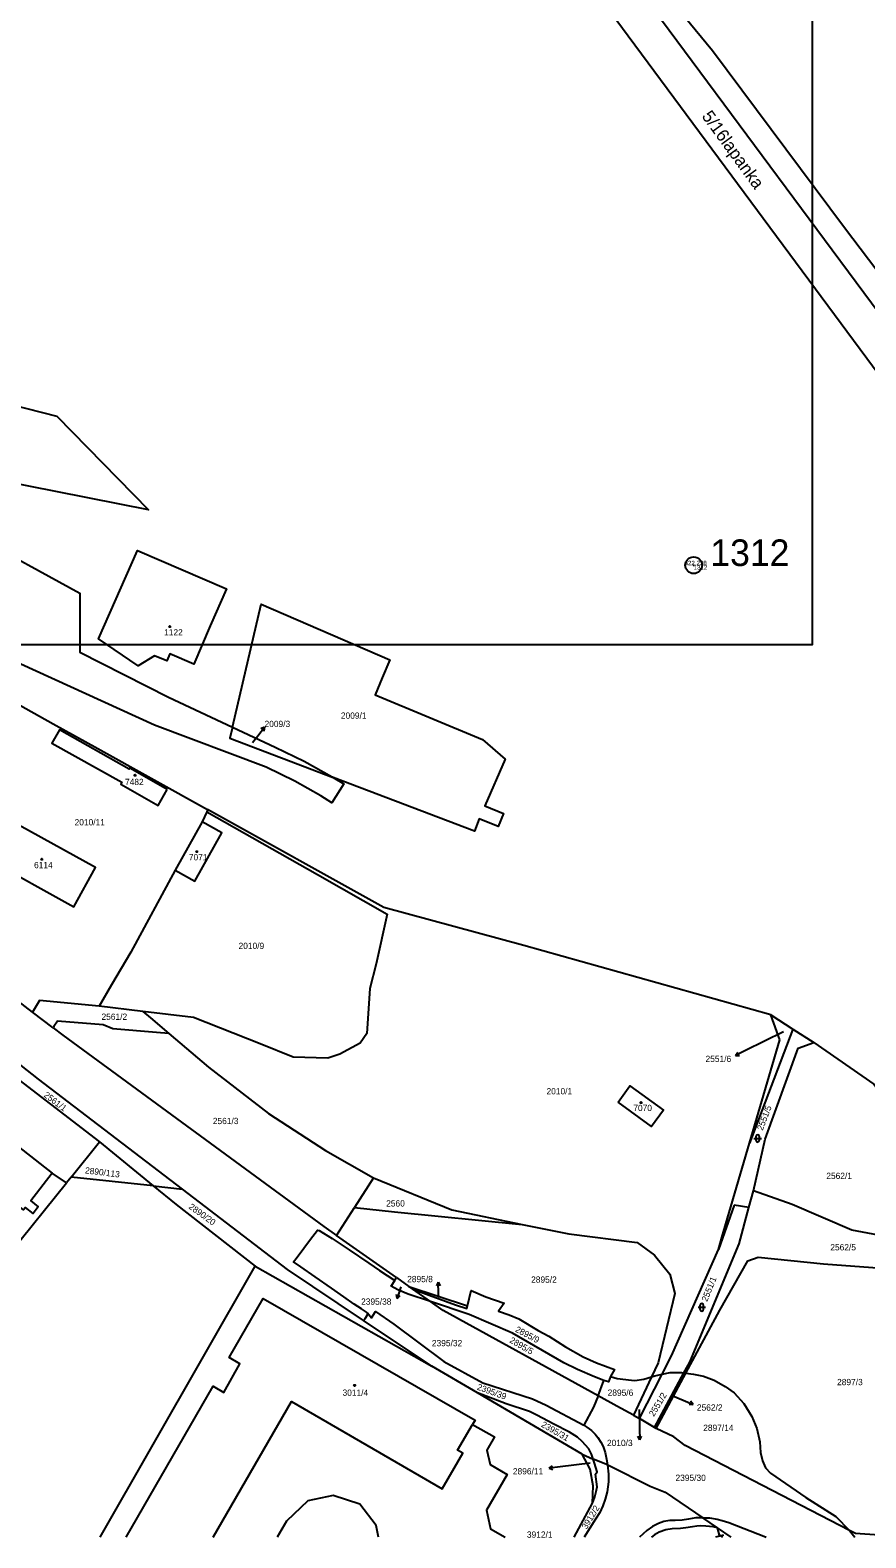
# Model space of a CAD drawing. Extents: x -667048 to -665920, y -1108425 to -1107247.
# Drawn here: x -666456.4 to -666229.9, y -1108425.3 to -1108016.8 of the extents above; entities that cross this region are included whole.
import ezdxf

# ---------------------------------------------------------------- set-up
doc = ezdxf.new("R2010")
doc.units = 0
for name, color, linetype in [('Default', 7, 'Continuous'), ('Hranice parcel', 7, 'Continuous'), ('Parcelní čísla', 7, 'Continuous'), ('Pop_ PČ_ popisy', 7, 'Continuous'), ('Vrstva 1', 7, 'Continuous'), ('Vrstva 2', 7, 'Continuous'), ('Vrstva 60', 7, 'Continuous'), ('Vrstva 61', 7, 'Continuous'), ('Značky budov', 7, 'Continuous'), ('Značky kultur', 7, 'Continuous')]:
    doc.layers.add(name, color=color, linetype=linetype)

# ---------------------------------------------------------------- blocks, each defined once
blk = doc.blocks.new('4.021')
at = {"layer": 'Default'}
blk.add_circle((-7, 1), 175, dxfattribs=at)
blk = doc.blocks.new('3.161')
at = {"layer": 'Default'}
for p, q in [((-1000, 1000), (1000, 1000)), ((-500, 1500), (-500, 500)), ((500, 500), (500, 1500))]:
    blk.add_line(p, q, dxfattribs=at)
for centre, start, end in [((0, 1500), 0, 180), ((0, 500), 180, 359.98789)]:
    blk.add_arc(centre, 500, start, end, dxfattribs=at)
blk = doc.blocks.new('10291')
at = {"layer": 'Default'}
for p, q in [((0, 3001), (-500, 2001)), ((0, 1), (0, 3001)), ((0, 3001), (500, 2001))]:
    blk.add_line(p, q, dxfattribs=at)

msp = doc.modelspace()

# ---------------------------------------------------------------- linework, layer by layer
at = {"layer": 'Hranice parcel'}
for points in [[(-666367.6, -1107733.37), (-666382.25, -1107746.6), (-666386.05, -1107757.21), (-666386.95, -1107822.21), (-666377, -1107854.78), (-666312.82, -1107976.82), (-666211.46, -1108113.47), (-666205.22, -1108120.66), (-666194.69, -1108126.35), (-666183.7, -1108127.05), (-666164.66, -1108121.36)], [(-666308.12, -1107969.91), (-666292.75, -1107996.41), (-666271.46, -1108022.33), (-666235.68, -1108070.26), (-666212.14, -1108101.26), (-666198.27, -1108121.92), (-666187.57, -1108125.3), (-666164.66, -1108121.36)], [(-666320.26, -1107983.17), (-666217.49, -1108122.07), (-666204.14, -1108132.75)], [(-666473.73, -1108137.06), (-666465.43, -1108117.23), (-666449.11, -1108121.4), (-666424.27, -1108146.74), (-666473.73, -1108137.06)], [(-666374.21, -1108219.28), (-666371.36, -1108220.98), (-666374.62, -1108226.13), (-666377.53, -1108224.23), (-666384.61, -1108220.26), (-666392.36, -1108216.54), (-666422.61, -1108205.11), (-666463.99, -1108186.24), (-666475.13, -1108181.04), (-666489.53, -1108173.36), (-666546.91, -1108141.77), (-666554.72, -1108137.47)], [(-666471.97, -1108153.48), (-666442.88, -1108169.37), (-666442.9, -1108185.32), (-666418.86, -1108197.5), (-666401.5, -1108205.65)], [(-666407.58, -1108178.17), (-666412.03, -1108188.62), (-666418.53, -1108185.84), (-666419.34, -1108187.72), (-666422.62, -1108186.32), (-666427.12, -1108189.02), (-666437.79, -1108181.77), (-666427.3, -1108157.82), (-666403.13, -1108168.19), (-666407.58, -1108178.17)], [(-666401.5, -1108205.65), (-666393.74, -1108172.32), (-666358.86, -1108187.38), (-666360.92, -1108192.34), (-666362.84, -1108196.95), (-666333.78, -1108209.04), (-666327.62, -1108214.37), (-666333.14, -1108226.96), (-666328.04, -1108229.05), (-666329.5, -1108232.56), (-666334.63, -1108230.51), (-666335.97, -1108233.85), (-666374.21, -1108219.28)], [(-666466.46, -1108195.64), (-666450.09, -1108204.73), (-666437.99, -1108211.45)], [(-666419.21, -1108222.58), (-666429.35, -1108216.78), (-666429.5, -1108217), (-666448.42, -1108206.41), (-666450.49, -1108209.99), (-666431.49, -1108220.59), (-666431.79, -1108221.09), (-666421.66, -1108226.87), (-666419.21, -1108222.58)], [(-666401.5, -1108205.65), (-666402.19, -1108208.62), (-666374.21, -1108219.28)], [(-666401.5, -1108205.65), (-666389.91, -1108211.08), (-666382.07, -1108214.87), (-666374.46, -1108219.13), (-666374.21, -1108219.28)], [(-666437.99, -1108211.45), (-666408.25, -1108227.98)], [(-666408.25, -1108227.98), (-666408.51, -1108228.56)], [(-666255.62, -1108283.59), (-666322.55, -1108264.86), (-666360.48, -1108254.53), (-666408.25, -1108227.98)], [(-666455.68, -1108282.86), (-666482, -1108262.62), (-666523.39, -1108230.78)], [(-666467.96, -1108241.34), (-666444.49, -1108254.32), (-666438.63, -1108243.72), (-666462, -1108230.81), (-666467.96, -1108241.34)], [(-666408.51, -1108228.56), (-666378.44, -1108245.6), (-666359.63, -1108256.35), (-666362.62, -1108269.83), (-666364.28, -1108276.45), (-666365.14, -1108288.63), (-666366.89, -1108291.25), (-666372.41, -1108294.29), (-666375.66, -1108295.31), (-666385.09, -1108295.09), (-666394.04, -1108291.44), (-666412.1, -1108284.35), (-666425.85, -1108282.67)], [(-666417.09, -1108244.44), (-666411.76, -1108247.42), (-666404.44, -1108234.31), (-666409.74, -1108231.28)], [(-666409.74, -1108231.28), (-666417.09, -1108244.44)], [(-666408.51, -1108228.56), (-666409.74, -1108231.28)], [(-666417.09, -1108244.44), (-666429.08, -1108266.61), (-666434.28, -1108275.51), (-666437.63, -1108281.23)], [(-666415.08, -1108330.81), (-666454.07, -1108301), (-666489.57, -1108273.1)], [(-666491.9, -1108276.3), (-666437.54, -1108318.05)], [(-666437.63, -1108281.23), (-666453.83, -1108279.75), (-666455.68, -1108282.86)], [(-666425.85, -1108282.67), (-666437.63, -1108281.23)], [(-666450.14, -1108287.12), (-666455.68, -1108282.86)], [(-666418.73, -1108288.7), (-666422.12, -1108288.41), (-666433.93, -1108287.4), (-666436.57, -1108286.29), (-666448.94, -1108285.28), (-666449.93, -1108286.8), (-666450.14, -1108287.12)], [(-666425.85, -1108282.67), (-666423.75, -1108284.46), (-666418.73, -1108288.7)], [(-666255.62, -1108283.59), (-666249.63, -1108287.46)], [(-666253.19, -1108290.38), (-666255.62, -1108283.59)], [(-666450.14, -1108287.12), (-666447.53, -1108289.14), (-666376.75, -1108340.94), (-666373.31, -1108343.36)], [(-666418.73, -1108288.7), (-666408.04, -1108297.75), (-666391.74, -1108310.31)], [(-666249.63, -1108287.46), (-666261.4, -1108318.34)], [(-666249.63, -1108287.46), (-666243.99, -1108291.1)], [(-666261.4, -1108318.34), (-666253.19, -1108290.38)], [(-666260.35, -1108331.3), (-666257.12, -1108317.27), (-666248.18, -1108292.62), (-666243.99, -1108291.1)], [(-666243.99, -1108291.1), (-666227.7, -1108302.43), (-666213.72, -1108320.63), (-666200.9, -1108335.77)], [(-666482.29, -1108301.57), (-666450.39, -1108326.54)], [(-666296.97, -1108307.26), (-666293.81, -1108302.8), (-666284.72, -1108309.42), (-666287.91, -1108313.84), (-666296.97, -1108307.26)], [(-666450.39, -1108326.54), (-666456.2, -1108333.99), (-666454.16, -1108335.65), (-666455.55, -1108337.43), (-666457.59, -1108335.76), (-666458.13, -1108336.46), (-666493.26, -1108308.83)], [(-666391.74, -1108310.31), (-666376.27, -1108320.34), (-666363.26, -1108327.81)], [(-666445.24, -1108327.58), (-666437.54, -1108318.05)], [(-666437.54, -1108318.05), (-666422.97, -1108329.91)], [(-666268.91, -1108343.91), (-666261.4, -1108318.34)], [(-666477.13, -1108367.05), (-666446.5, -1108329.13)], [(-666446.5, -1108329.13), (-666450.39, -1108326.54)], [(-666445.24, -1108327.58), (-666446.5, -1108329.13)], [(-666422.97, -1108329.91), (-666445.24, -1108327.58)], [(-666422.97, -1108329.91), (-666416.75, -1108334.97), (-666395.38, -1108351.66)], [(-666422.97, -1108329.91), (-666415.08, -1108330.81)], [(-666363.26, -1108327.81), (-666368.45, -1108335.83)], [(-666363.26, -1108327.81), (-666342.05, -1108336.4), (-666322.97, -1108340.44)], [(-666386.59, -1108352.59), (-666415.08, -1108330.81)], [(-666261.55, -1108335.79), (-666260.35, -1108331.3)], [(-666205.05, -1108348.04), (-666220.61, -1108344.36), (-666233.7, -1108341.93), (-666249.84, -1108334.97), (-666260.35, -1108331.3)], [(-666373.31, -1108343.36), (-666368.45, -1108335.83)], [(-666368.45, -1108335.83), (-666357.58, -1108336.96), (-666322.97, -1108340.44)], [(-666279.15, -1108380.61), (-666277.57, -1108377.67), (-666264.17, -1108345.61), (-666261.55, -1108335.79)], [(-666265.59, -1108335.2), (-666269.83, -1108347.17)], [(-666261.55, -1108335.79), (-666265.59, -1108335.2)], [(-666364.9, -1108364.38), (-666366.57, -1108363.3), (-666368.57, -1108362.01), (-666371.33, -1108359.99), (-666374.7, -1108357.64), (-666379.11, -1108354.57), (-666383, -1108351.88), (-666384.97, -1108350.52), (-666384.03, -1108349.28), (-666380.36, -1108344.41), (-666378.47, -1108341.91), (-666378, -1108342.01), (-666374.5, -1108344.22), (-666369.85, -1108347.27), (-666364.53, -1108350.86), (-666361.71, -1108352.83), (-666357.56, -1108355.54)], [(-666322.97, -1108340.44), (-666310.32, -1108342.9), (-666291.83, -1108345.28), (-666287.13, -1108348.72), (-666283.03, -1108353.89), (-666281.62, -1108359.1), (-666286.15, -1108377.89), (-666287.92, -1108381.66)], [(-666357.1, -1108354.78), (-666373.31, -1108343.36)], [(-666269.83, -1108347.17), (-666268.91, -1108343.91)], [(-666285.07, -1108380.95), (-666282.51, -1108375.95), (-666269.83, -1108347.17)], [(-666278.65, -1108380.68), (-666269.46, -1108363.62), (-666261.84, -1108350.27), (-666259.02, -1108349.27), (-666241.32, -1108351.03), (-666206.04, -1108353.64)], [(-666437.4, -1108425.13), (-666395.38, -1108351.66)], [(-666395.38, -1108351.66), (-666347.5, -1108378.83)], [(-666366, -1108366.41), (-666386.59, -1108352.59)], [(-666357.56, -1108355.54), (-666357.1, -1108354.78)], [(-666357.1, -1108354.78), (-666353.7, -1108357.17)], [(-666347.85, -1108361.27), (-666353.88, -1108359.26), (-666356.74, -1108358.14), (-666358.52, -1108357.13), (-666357.56, -1108355.54)], [(-666353.7, -1108357.17), (-666337.81, -1108362.46)], [(-666352.64, -1108357.91), (-666353.7, -1108357.17)], [(-666352.64, -1108357.91), (-666341.1, -1108362.21), (-666337.98, -1108363.21), (-666337.81, -1108362.46)], [(-666347.85, -1108361.27), (-666352.64, -1108357.91)], [(-666337.81, -1108362.46), (-666336.87, -1108358.32), (-666332.81, -1108360.01), (-666327.86, -1108361.7), (-666329.44, -1108363.85), (-666326.55, -1108364.92), (-666323.95, -1108365.97), (-666318.63, -1108369.09), (-666315.78, -1108370.67), (-666311.26, -1108373.59), (-666306.46, -1108376.27), (-666302.83, -1108377.87), (-666297.96, -1108379.71), (-666299.11, -1108381.58)], [(-666430.36, -1108425.13), (-666406.75, -1108384.24), (-666403.85, -1108385.91), (-666399.54, -1108378.12), (-666402.4, -1108376.48), (-666393.2, -1108360.44), (-666335.78, -1108393.39), (-666336.48, -1108394.61)], [(-666302.44, -1108386.81), (-666344.42, -1108363.68), (-666347.85, -1108361.27)], [(-666300.83, -1108382.64), (-666303.4, -1108381.69), (-666308.04, -1108379.73), (-666311.68, -1108377.92), (-666325.67, -1108369.89), (-666337.35, -1108364.78), (-666347.85, -1108361.27)], [(-666366, -1108366.41), (-666365.6, -1108365.88), (-666364.88, -1108364.87), (-666364.9, -1108364.38)], [(-666347.5, -1108378.83), (-666366, -1108366.41)], [(-666364.9, -1108364.38), (-666363.86, -1108365.68), (-666362.8, -1108363.95), (-666357.8, -1108367.37), (-666344.24, -1108377.57), (-666333.66, -1108383.3), (-666320.2, -1108387.65), (-666316.52, -1108389.38), (-666306.33, -1108394.82)], [(-666335.15, -1108386.04), (-666347.5, -1108378.83)], [(-666302.44, -1108386.81), (-666300.83, -1108382.64)], [(-666299.11, -1108381.58), (-666299.57, -1108383.03), (-666300.83, -1108382.64)], [(-666299.11, -1108381.58), (-666297.29, -1108382.14), (-666293.34, -1108382.55), (-666292.5, -1108382.65), (-666290.01, -1108382.34), (-666287.92, -1108381.66)], [(-666287.92, -1108381.66), (-666292.79, -1108392.06)], [(-666291.22, -1108392.99), (-666285.07, -1108380.95)], [(-666287.92, -1108381.66), (-666287.06, -1108381.38), (-666285.07, -1108380.95)], [(-666287.11, -1108395.41), (-666279.15, -1108380.61)], [(-666286.71, -1108395.64), (-666278.65, -1108380.68)], [(-666285.07, -1108380.95), (-666282.87, -1108380.48), (-666279.71, -1108380.54), (-666279.15, -1108380.61)], [(-666279.15, -1108380.61), (-666278.65, -1108380.68)], [(-666278.65, -1108380.68), (-666276.59, -1108380.95), (-666273.9, -1108381.53), (-666270.98, -1108382.57), (-666267.98, -1108384.28), (-666265.59, -1108386), (-666262.9, -1108388.91), (-666260.76, -1108392.4), (-666259.4, -1108395.64), (-666258.58, -1108399.31), (-666258.44, -1108402.2), (-666257.89, -1108404.42), (-666257.05, -1108406.31), (-666255.7, -1108407.75), (-666246.1, -1108414.35), (-666238.04, -1108419.48), (-666234.25, -1108423.31)], [(-666303.74, -1108403.96), (-666304.19, -1108402.61), (-666304.9, -1108401.22), (-666306.72, -1108399.17), (-666308.02, -1108398.06), (-666310.21, -1108396.65), (-666314.41, -1108394.48), (-666319.01, -1108392.11), (-666321.04, -1108391.06), (-666327.38, -1108388.99), (-666335.15, -1108386.04)], [(-666306.78, -1108402.61), (-666335.15, -1108386.04)], [(-666302.44, -1108386.81), (-666303.64, -1108389.92), (-666306.33, -1108394.82)], [(-666292.79, -1108392.06), (-666297.33, -1108389.63), (-666302.44, -1108386.81)], [(-666406.78, -1108425.13), (-666385.55, -1108388.35), (-666344.66, -1108411.98), (-666341.45, -1108406.44), (-666339.09, -1108402.36), (-666340.5, -1108401.55), (-666336.48, -1108394.61)], [(-666336.48, -1108394.61), (-666330.52, -1108397.91), (-666332.57, -1108401.53), (-666331.7, -1108405.44), (-666327.05, -1108408.18), (-666332.64, -1108417.78), (-666331.62, -1108422.9), (-666327.57, -1108425.13)], [(-666306.33, -1108394.82), (-666305.51, -1108395.28), (-666304.25, -1108396.24), (-666303.25, -1108397.23), (-666302.51, -1108398.11), (-666301.7, -1108399.37), (-666301.09, -1108400.54), (-666300.51, -1108402.17), (-666300.16, -1108403.95), (-666299.9, -1108405.54)], [(-666292.79, -1108392.06), (-666291.22, -1108392.99)], [(-666287.11, -1108395.41), (-666291.22, -1108392.99)], [(-666286.71, -1108395.64), (-666287.11, -1108395.41)], [(-666234.25, -1108423.31), (-666278.79, -1108400.31), (-666281.92, -1108397.97), (-666286.71, -1108395.64)], [(-666303.92, -1108415.9), (-666303.73, -1108411.23), (-666304.56, -1108406.7), (-666306.78, -1108402.61)], [(-666306.78, -1108402.61), (-666303.74, -1108403.96)], [(-666299.9, -1108405.54), (-666299.59, -1108408.06), (-666299.62, -1108410.12), (-666299.76, -1108411.51), (-666299.97, -1108412.84), (-666300.49, -1108414.85), (-666301.1, -1108416.66), (-666301.93, -1108418.4), (-666303.11, -1108420.24), (-666306.16, -1108425.13)], [(-666303.92, -1108415.9), (-666303.34, -1108414.22), (-666302.92, -1108412.73), (-666302.68, -1108411.47), (-666303.12, -1108408.08), (-666302.66, -1108407.46), (-666303.39, -1108405.04), (-666303.74, -1108403.96)], [(-666299.9, -1108405.54), (-666303.74, -1108403.96)], [(-666299.9, -1108405.54), (-666299.4, -1108405.74), (-666288.36, -1108411.3), (-666284.24, -1108412.95), (-666274.07, -1108419.88)], [(-666361.9, -1108425.13), (-666362.54, -1108421.93), (-666367.04, -1108416.19), (-666374.25, -1108413.84), (-666381.11, -1108415.25), (-666386.9, -1108420.76), (-666389.42, -1108425.13)], [(-666308.94, -1108425.13), (-666303.92, -1108415.9)], [(-666274.07, -1108419.88), (-666275.9, -1108419.91), (-666277.94, -1108420.2), (-666279.68, -1108420.47), (-666281.52, -1108420.56), (-666282.99, -1108420.62), (-666284.62, -1108420.91), (-666286.08, -1108421.41), (-666287.68, -1108422.2), (-666289.26, -1108423.32), (-666291.17, -1108425.13)], [(-666274.07, -1108419.88), (-666272.27, -1108419.9), (-666270.12, -1108420.23), (-666268.76, -1108420.57), (-666267.02, -1108421.16), (-666262.8, -1108422.81), (-666257.54, -1108424.88), (-666256.92, -1108425.13)], [(-666270.11, -1108422.58), (-666274.07, -1108419.88)], [(-666270.11, -1108422.58), (-666271.23, -1108422.32), (-666273.22, -1108422.1), (-666274.61, -1108422.09), (-666275.67, -1108422.17), (-666276.81, -1108422.33), (-666278.65, -1108422.62), (-666280.06, -1108422.75), (-666282.31, -1108422.84), (-666284.08, -1108423.09), (-666285.84, -1108423.73), (-666287.14, -1108424.53), (-666287.94, -1108425.11), (-666287.96, -1108425.13)], [(-666266.36, -1108425.13), (-666270.11, -1108422.58)], [(-666268.61, -1108425.13), (-666269.55, -1108424.58), (-666270.11, -1108422.58)], [(-666226.29, -1108424.56), (-666232.68, -1108424.12), (-666234.25, -1108423.31)], [(-666234.25, -1108423.31), (-666232.82, -1108425.13)], [(-666308.94, -1108425.13), (-666308.94, -1108425.13)], [(-666308.94, -1108425.13), (-666308.94, -1108425.13)]]:
    msp.add_lwpolyline(points, dxfattribs=at)
at = {"layer": 'Pop_ PČ_ popisy'}
for points in [[(-666396.06, -1108209.81), (-666394.67, -1108208.01)], [(-666252.14, -1108288.25), (-666262.5, -1108293.3)], [(-666355.87, -1108357.29), (-666355.97, -1108357.6)], [(-666345.6, -1108360.16), (-666345.66, -1108359.04)], [(-666282.14, -1108386.79), (-666279.41, -1108387.96)], [(-666291.27, -1108390.49), (-666291.21, -1108395.74)], [(-666304.61, -1108405.06), (-666312.75, -1108406.06)], [(-666268.46, -1108424.55), (-666270.6, -1108425.13)]]:
    msp.add_lwpolyline(points, dxfattribs=at)
at = {"layer": 'Vrstva 1'}
msp.add_line((-666276.68, -1108161.79), (-666276.38, -1108161.79), dxfattribs=at)
msp.add_circle((-666276.53, -1108161.79), 2.27, dxfattribs=at)
at = {"layer": 'Vrstva 2'}
msp.add_lwpolyline([(-666838.39, -1107343.37), (-666244.39, -1107343.37), (-666244.39, -1108183.37), (-666838.39, -1108183.37)], close=True, dxfattribs=at)
at = {"layer": 'Vrstva 60'}
for p, q in [((-666276.53, -1108161.79), (-666276.53, -1108161.79)), ((-666276.51, -1108161.79), (-666276.51, -1108161.79))]:
    msp.add_line(p, q, dxfattribs=at)

# ---------------------------------------------------------------- block references
at = {"layer": 'Pop_ PČ_ popisy'}
for p, xscale, yscale, rotation in [((-666394.67, -1108208.01), 0.0010000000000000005, 0.0010000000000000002, -38.00000002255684), ((-666262.5, -1108293.3), 0.001, 0.0010000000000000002, 116.0000000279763), ((-666355.97, -1108357.6), 0.0010000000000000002, 0.0010000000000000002, 162.00000007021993), ((-666345.66, -1108359.04), 0.001, 0.0010000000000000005, 2.9999999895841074), ((-666279.41, -1108387.96), 0.0010000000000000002, 0.001, -113.0000000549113), ((-666291.21, -1108395.74), 0.0010000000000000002, 0.0010000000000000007, -179.00000011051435), ((-666312.75, -1108406.06), 0.0010000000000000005, 0.0010000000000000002, 97.00000001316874)]:
    msp.add_blockref('10291', p, dxfattribs=dict(at, xscale=xscale, yscale=yscale, rotation=rotation))
at = {"layer": 'Značky budov', "xscale": 0.0010000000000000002, "yscale": 0.0010000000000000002}
for p in [(-666418.48, -1108178.41), (-666427.9, -1108218.69), (-666411.17, -1108239.4), (-666453.17, -1108241.46), (-666290.78, -1108307.38), (-666368.42, -1108384.01)]:
    msp.add_blockref('4.021', p, dxfattribs=at)
at = {"layer": 'Značky kultur', "xscale": 0.0010000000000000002, "yscale": 0.0010000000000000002}
for p in [(-666259.18, -1108318.09), (-666274.32, -1108363.85)]:
    msp.add_blockref('3.161', p, dxfattribs=at)

# ---------------------------------------------------------------- texts
at = {"layer": 'Parcelní čísla'}
for s, p in [('1122', (-666420.05, -1108180.82)), ('2009/1', (-666372.14, -1108203.39)), ('2009/3', (-666392.83, -1108205.64)), ('7482', (-666430.65, -1108221.36)), ('2010/11', (-666444.31, -1108232.28)), ('7071', (-666413.34, -1108241.76)), ('6114', (-666455.3, -1108243.88)), ('2010/9', (-666399.87, -1108265.77)), ('2561/2', (-666437.01, -1108284.96)), ('2551/6', (-666273.31, -1108296.38)), ('2010/1', (-666316.41, -1108305.16)), ('7070', (-666292.89, -1108309.68)), ('2561/3', (-666406.85, -1108313.21)), ('2562/1', (-666240.58, -1108328.08)), ('2560', (-666359.86, -1108335.54)), ('2562/5', (-666239.49, -1108347.43)), ('2895/8', (-666354.17, -1108356.04)), ('2895/2', (-666320.58, -1108356.19)), ('2395/38', (-666366.66, -1108362.15)), ('2395/32', (-666347.47, -1108373.39)), ('2897/3', (-666237.66, -1108383.94)), ('3011/4', (-666371.69, -1108386.82)), ('2895/6', (-666299.84, -1108386.82)), ('2562/2', (-666275.65, -1108390.84)), ('2562/2', (-666275.65, -1108390.84)), ('2562/2', (-666275.65, -1108390.84)), ('2562/2', (-666275.65, -1108390.84)), ('2562/2', (-666275.65, -1108390.84)), ('2562/2', (-666275.65, -1108390.84)), ('2897/14', (-666273.94, -1108396.33)), ('2010/3', (-666300.02, -1108400.44)), ('2010/3', (-666300.02, -1108400.44)), ('2010/3', (-666300.02, -1108400.44)), ('2010/3', (-666300.02, -1108400.44)), ('2010/3', (-666300.02, -1108400.44)), ('2010/3', (-666300.02, -1108400.44)), ('2010/3', (-666300.02, -1108400.44)), ('2010/3', (-666300.02, -1108400.44)), ('2010/3', (-666300.02, -1108400.44)), ('2896/11', (-666325.52, -1108408.12)), ('2395/30', (-666281.45, -1108409.88)), ('3912/1', (-666321.72, -1108425.28)), ('3912/1', (-666321.72, -1108425.28))]:
    msp.add_text(s, height=1.7, dxfattribs=at).set_placement(p)
for s, rotation, p in [('2561/1', 323, (-666452.81, -1108305.67)), ('2551/5', 69, (-666257.83, -1108315.06)), ('2890/113', 353, (-666441.57, -1108326.54)), ('2890/20', 324, (-666413.53, -1108335.93)), ('2551/1', 68, (-666272.88, -1108361.43)), ('2895/5', 330, (-666326.59, -1108372.25)), ('2895/9', 332, (-666325.05, -1108369.36)), ('2395/39', 340, (-666335.38, -1108385.1)), ('2551/2', 59, (-666287.31, -1108392.57)), ('2395/31', 330, (-666318.01, -1108395.09)), ('3912/2', 59, (-666305.53, -1108423.11))]:
    msp.add_text(s, height=1.7, rotation=rotation, dxfattribs=at).set_placement(p)
at = {"layer": 'Pop_ PČ_ popisy'}
msp.add_text('5/16lapanka', height=3.4, rotation=306, dxfattribs=at).set_placement((-666274.48, -1108040.16))
at = {"layer": 'Vrstva 1'}
msp.add_text('1312', height=7.2, dxfattribs=at).set_placement((-666272, -1108162))
at = {"layer": 'Vrstva 60'}
for p in [(-666276.53, -1108162.99), (-666276.51, -1108162.99)]:
    msp.add_text('1312', height=1.2, dxfattribs=at).set_placement(p)
at = {"layer": 'Vrstva 61'}
for s, p in [('422.220', (-666278.98, -1108161.79)), ('422.218', (-666278.96, -1108161.79))]:
    msp.add_text(s, height=1.2, dxfattribs=at).set_placement(p)

doc.saveas('drawing.dxf')
